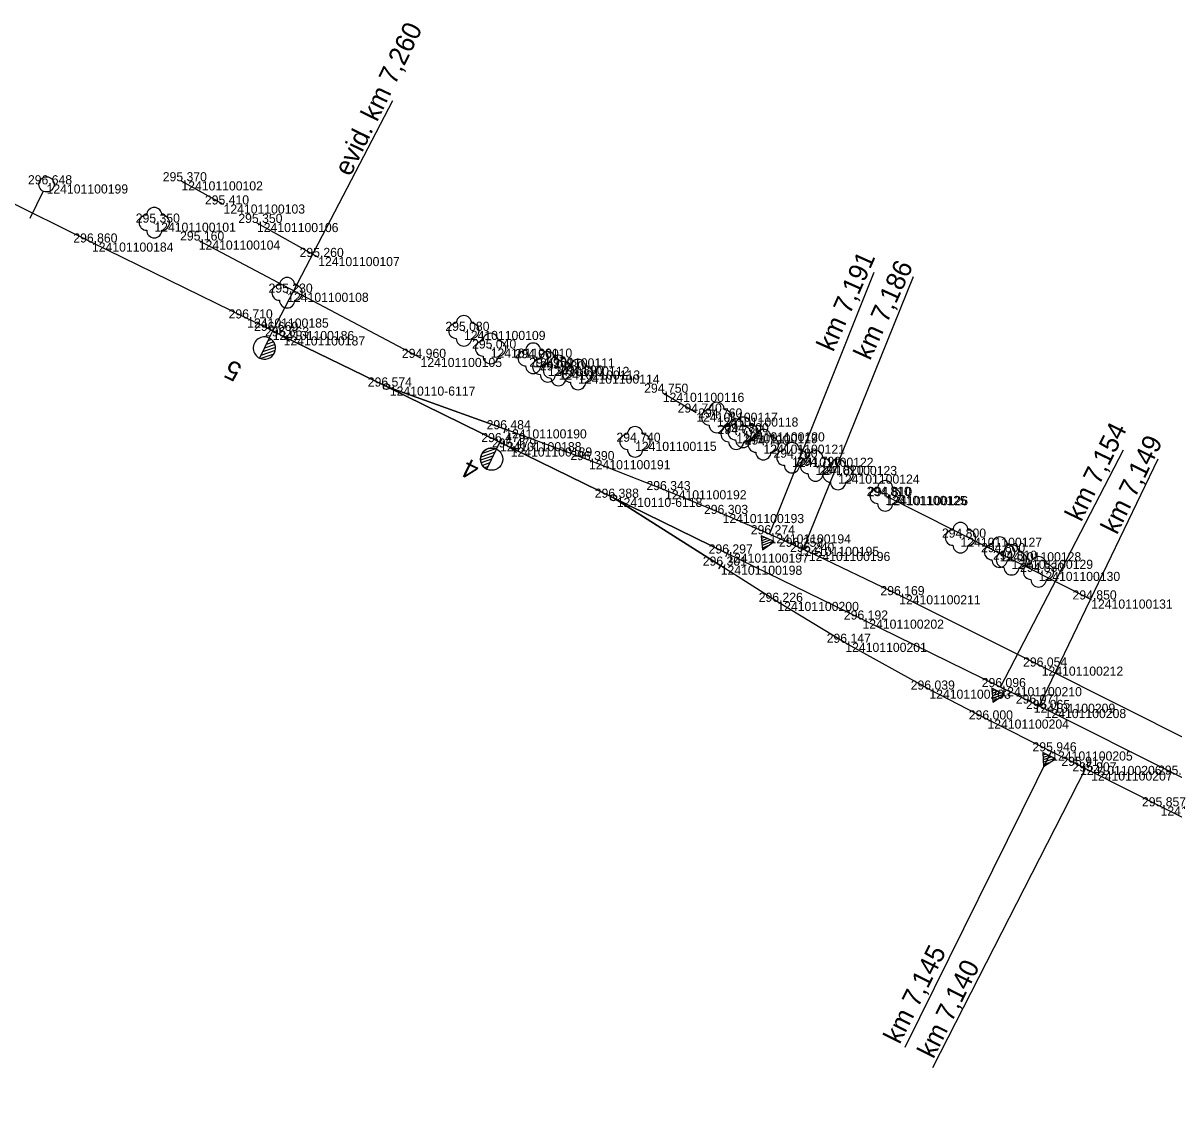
# Model space of a CAD drawing. Extents: x -616949 to -607976, y -1164436 to -1159224.
# Drawn here: x -613594.6 to -613443.4, y -1161463 to -1161320.7 of the extents above; entities that cross this region are included whole.
import ezdxf

# ---------------------------------------------------------------- set-up
doc = ezdxf.new("R2010")
doc.units = 0
for name, color, linetype in [('Vrstva 1', 7, 'Continuous'), ('Vrstva 2', 7, 'Continuous'), ('Vrstva 3', 7, 'Continuous'), ('Vrstva 37', 7, 'Continuous'), ('Vrstva 49', 7, 'Continuous'), ('Vrstva 50', 7, 'Continuous'), ('Vrstva 60', 7, 'Continuous'), ('Vrstva 61', 7, 'Continuous')]:
    doc.layers.add(name, color=color, linetype=linetype)

msp = doc.modelspace()

# ---------------------------------------------------------------- linework, layer by layer
at = {"layer": 'Vrstva 1'}
for points in [[(-613561.83, -1161361.12), (-613565.18, -1161359.48), (-613585.58, -1161349.51), (-613606, -1161339.42)], [(-613531.97, -1161375.72), (-613546.89, -1161368.42), (-613560.4, -1161361.83), (-613561.83, -1161361.12)], [(-613349.94, -1161460.64), (-613371.44, -1161449.88), (-613393.22, -1161439), (-613418.97, -1161426.12), (-613440.8, -1161415.2), (-613460.8, -1161405.2), (-613479.53, -1161395.83), (-613491.4, -1161390.14), (-613492.87, -1161389.47), (-613496.57, -1161387.83), (-613502.72, -1161385.16), (-613510.28, -1161382.03), (-613520.28, -1161378.09), (-613531.28, -1161374.04), (-613546.89, -1161368.42), (-613560.4, -1161361.83), (-613561.83, -1161361.12)], [(-613170.83, -1161560.95), (-613193.86, -1161549.42), (-613216.58, -1161538.05), (-613238.41, -1161527.12), (-613261.08, -1161515.78), (-613282.87, -1161504.88), (-613306.41, -1161493.08), (-613329.58, -1161481.52), (-613354.95, -1161468.79), (-613375.86, -1161458.34), (-613397.09, -1161447.7), (-613423.08, -1161434.66), (-613445.18, -1161423.56), (-613454.31, -1161418.97), (-613455.76, -1161418.24), (-613459.55, -1161416.34), (-613467.93, -1161412.15), (-613475.56, -1161408.23), (-613486.6, -1161402.08), (-613495.53, -1161396.7), (-613502.97, -1161391.95), (-613517.07, -1161383.03), (-613530.57, -1161376.42), (-613531.97, -1161375.72)], [(-613169.01, -1161556.54), (-613191.83, -1161545.12), (-613214.2, -1161533.93), (-613236.35, -1161522.85), (-613258.71, -1161511.65), (-613281.11, -1161500.45), (-613304.08, -1161488.95), (-613327.59, -1161477.18), (-613352.38, -1161464.78), (-613374.13, -1161453.9), (-613400.96, -1161440.47), (-613420.84, -1161430.52), (-613443.07, -1161419.4), (-613460.41, -1161410.77), (-613461.85, -1161410.06), (-613466.23, -1161407.9), (-613484.35, -1161399.03), (-613502.11, -1161390.35), (-613517.07, -1161383.03), (-613530.57, -1161376.42), (-613531.97, -1161375.72)]]:
    msp.add_lwpolyline(points, dxfattribs=at)
at = {"layer": 'Vrstva 2'}
for p, q in [((-613561.83, -1161361.12), (-613546.03, -1161330.84)), ((-613562.28, -1161362.05), (-613561.83, -1161361.12)), ((-613562.28, -1161362.05), (-613563.56, -1161364.68)), ((-613561.53, -1161362.91), (-613562.93, -1161363.4)), ((-613561.7, -1161362.57), (-613562.7, -1161362.91)), ((-613561.97, -1161362.26), (-613562.46, -1161362.43)), ((-613561.5, -1161363.71), (-613563.4, -1161364.36)), ((-613561.7, -1161364.18), (-613563.38, -1161364.76)), ((-613561.46, -1161363.29), (-613563.17, -1161363.88)), ((-613546.89, -1161368.42), (-613531.28, -1161374.04)), ((-613531.44, -1161374.51), (-613531.11, -1161373.57)), ((-613532.53, -1161376.61), (-613534.32, -1161377.22)), ((-613533.71, -1161379.28), (-613532.42, -1161376.65)), ((-613532.42, -1161376.65), (-613531.97, -1161375.72)), ((-613531.75, -1161375.27), (-613532.19, -1161376.17)), ((-613532.84, -1161377.51), (-613534.52, -1161378.08)), ((-613532.61, -1161377.03), (-613534.5, -1161377.68)), ((-613533.08, -1161377.98), (-613534.44, -1161378.45)), ((-613533.31, -1161378.46), (-613534.27, -1161378.79)), ((-613533.54, -1161378.94), (-613533.99, -1161379.09)), ((-613517.07, -1161383.03), (-613502.97, -1161391.95)), ((-613501.89, -1161389.9), (-613502.33, -1161390.8)), ((-613503.24, -1161392.37), (-613502.7, -1161391.53))]:
    msp.add_line(p, q, dxfattribs=at)
for points in [[(-613561.83, -1161361.12), (-613560.4, -1161361.83), (-613546.89, -1161368.42), (-613531.97, -1161375.72)], [(-613559.42, -1161362.02), (-613560.4, -1161361.83), (-613559.64, -1161362.48)], [(-613531.97, -1161375.72), (-613530.57, -1161376.42), (-613517.07, -1161383.03), (-613502.11, -1161390.35)], [(-613529.59, -1161376.62), (-613530.57, -1161376.42), (-613529.81, -1161377.08)]]:
    msp.add_lwpolyline(points, dxfattribs=at)
for centre, radius in [((-613546.89, -1161368.42), 0.4), ((-613533.07, -1161377.96), 1.46), ((-613517.07, -1161383.03), 0.4)]:
    msp.add_circle(centre, radius, dxfattribs=at)
for centre, start, end in [((-613562.93, -1161363.37), 63.7905, 244.26), ((-613562.92, -1161363.37), 244.0448, 64.0057), ((-613533.07, -1161377.96), 63.9691, 243.93)]:
    msp.add_arc(centre, 1.46, start, end, dxfattribs=at)
at = {"layer": 'Vrstva 3'}
for p, q in [((-613496.57, -1161387.83), (-613482.79, -1161353.4)), ((-613492.14, -1161389.81), (-613477.65, -1161353.99)), ((-613466.23, -1161407.9), (-613450.06, -1161376.73)), ((-613461.13, -1161410.42), (-613445.51, -1161377.91)), ((-613497.23, -1161388.21), (-613497.62, -1161388.36)), ((-613496.83, -1161388.39), (-613497.59, -1161388.68)), ((-613496.43, -1161388.56), (-613497.56, -1161389)), ((-613496.03, -1161388.74), (-613497.52, -1161389.31)), ((-613496.79, -1161389.35), (-613497.49, -1161389.63)), ((-613491.4, -1161390.14), (-613492.87, -1161389.47)), ((-613466.9, -1161408.26), (-613467.31, -1161408.39)), ((-613466.51, -1161408.45), (-613467.29, -1161408.72)), ((-613466.13, -1161408.64), (-613467.27, -1161409.03)), ((-613465.73, -1161408.83), (-613467.24, -1161409.35)), ((-613466.51, -1161409.42), (-613467.22, -1161409.67)), ((-613460.41, -1161410.77), (-613461.85, -1161410.06)), ((-613459.55, -1161416.34), (-613478.8, -1161455.25)), ((-613460.23, -1161416.69), (-613460.63, -1161416.82)), ((-613459.84, -1161416.88), (-613460.62, -1161417.14)), ((-613459.46, -1161417.07), (-613460.6, -1161417.46)), ((-613459.06, -1161417.27), (-613460.58, -1161417.77)), ((-613455.04, -1161418.6), (-613475.15, -1161457.89)), ((-613459.85, -1161417.85), (-613460.56, -1161418.09)), ((-613454.31, -1161418.97), (-613455.76, -1161418.24))]:
    msp.add_line(p, q, dxfattribs=at)
for points in [[(-613497.47, -1161389.85), (-613495.97, -1161388.77), (-613497.66, -1161388.01)], [(-613467.21, -1161409.89), (-613465.67, -1161408.87), (-613467.33, -1161408.05)], [(-613460.55, -1161418.32), (-613459, -1161417.3), (-613460.66, -1161416.47)]]:
    msp.add_lwpolyline(points, close=True, dxfattribs=at)
at = {"layer": 'Vrstva 37'}
for p, q in [((-613591.54, -1161341.87), (-613591.54, -1161341.87)), ((-613591.98, -1161342.77), (-613593.75, -1161346.35))]:
    msp.add_line(p, q, dxfattribs=at)
msp.add_circle((-613591.54, -1161341.87), 1, dxfattribs=at)
at = {"layer": 'Vrstva 49'}
for p, q in [((-613563.9, -1161346.94), (-613555.85, -1161351.41)), ((-613571.55, -1161349.24), (-613542.41, -1161364.66)), ((-613510.58, -1161369.24), (-613506.18, -1161371.85)), ((-613481.18, -1161382.83), (-613454.3, -1161396.39))]:
    msp.add_line(p, q, dxfattribs=at)
msp.add_lwpolyline([(-613568.29, -1161344.51), (-613573.83, -1161341.47)], dxfattribs=at)
at = {"layer": 'Vrstva 50'}
for p, q in [((-613577.45, -1161346.9), (-613577.31, -1161346.9)), ((-613560, -1161356.1), (-613559.86, -1161356.1)), ((-613536.77, -1161361.11), (-613536.63, -1161361.11)), ((-613533.26, -1161363.43), (-613533.11, -1161363.43)), ((-613527.67, -1161364.71), (-613527.53, -1161364.71)), ((-613525.75, -1161365.83), (-613525.61, -1161365.83)), ((-613524.34, -1161366.31), (-613524.2, -1161366.31)), ((-613521.78, -1161366.85), (-613521.64, -1161366.85)), ((-613503.55, -1161372.49), (-613503.41, -1161372.49)), ((-613501, -1161374.67), (-613500.86, -1161374.67)), ((-613500.08, -1161374.43), (-613499.94, -1161374.43)), ((-613514.29, -1161375.68), (-613514.15, -1161375.68)), ((-613497.43, -1161376.05), (-613497.29, -1161376.05)), ((-613493.67, -1161377.77), (-613493.53, -1161377.77)), ((-613490.58, -1161378.85), (-613490.44, -1161378.85)), ((-613487.62, -1161379.98), (-613487.48, -1161379.98)), ((-613481.42, -1161382.78), (-613481.28, -1161382.78)), ((-613471.53, -1161388.27), (-613471.39, -1161388.27)), ((-613466.39, -1161390.18), (-613466.25, -1161390.18)), ((-613464.83, -1161391.17), (-613464.69, -1161391.17)), ((-613461.27, -1161392.76), (-613461.13, -1161392.76))]:
    msp.add_line(p, q, dxfattribs=at)
for centre, start, end in [((-613577.39, -1161345.9), 0, 180), ((-613578.39, -1161346.9), 90, 270), ((-613576.39, -1161346.9), 270, 90), ((-613577.39, -1161347.9), 180, 0), ((-613560.94, -1161356.1), 90, 270), ((-613559.94, -1161355.1), 0, 180), ((-613558.94, -1161356.1), 270, 90), ((-613559.94, -1161357.1), 180, 0), ((-613537.71, -1161361.11), 90, 270), ((-613536.71, -1161360.11), 0, 180), ((-613535.71, -1161361.11), 270, 90), ((-613533.2, -1161362.43), 0, 180), ((-613536.71, -1161362.11), 180, 0), ((-613534.2, -1161363.43), 90, 270), ((-613532.2, -1161363.43), 270, 90), ((-613527.61, -1161363.71), 0, 180), ((-613533.2, -1161364.43), 180, 0), ((-613528.61, -1161364.71), 90, 270), ((-613525.69, -1161364.83), 0, 180), ((-613526.61, -1161364.71), 270, 90), ((-613524.28, -1161365.31), 0, 180), ((-613527.61, -1161365.71), 180, 0), ((-613526.69, -1161365.83), 90, 270), ((-613525.28, -1161366.31), 90, 270), ((-613524.69, -1161365.83), 270, 90), ((-613522.72, -1161366.85), 90, 270), ((-613523.28, -1161366.31), 270, 90), ((-613521.72, -1161365.85), 0, 180), ((-613520.72, -1161366.85), 270, 90), ((-613525.69, -1161366.83), 180, 0), ((-613524.28, -1161367.31), 180, 0), ((-613521.72, -1161367.85), 180, 0), ((-613503.49, -1161371.49), 0, 180), ((-613504.49, -1161372.49), 90, 270), ((-613502.49, -1161372.49), 270, 90), ((-613514.23, -1161374.68), 0, 180), ((-613503.49, -1161373.49), 180, 0), ((-613501.94, -1161374.67), 90, 270), ((-613501.02, -1161374.43), 90, 270), ((-613500.94, -1161373.67), 0, 180), ((-613500.02, -1161373.43), 0, 180), ((-613499.94, -1161374.67), 270, 90), ((-613499.02, -1161374.43), 270, 90), ((-613515.23, -1161375.68), 90, 270), ((-613513.23, -1161375.68), 270, 90), ((-613498.37, -1161376.05), 90, 270), ((-613497.37, -1161375.05), 0, 180), ((-613496.37, -1161376.05), 270, 90), ((-613514.23, -1161376.68), 180, 0), ((-613500.94, -1161375.67), 180, 0), ((-613500.02, -1161375.43), 180, 0), ((-613493.61, -1161376.77), 0, 180), ((-613497.37, -1161377.05), 180, 0), ((-613494.61, -1161377.77), 90, 270), ((-613492.61, -1161377.77), 270, 90), ((-613491.52, -1161378.85), 90, 270), ((-613490.52, -1161377.85), 0, 180), ((-613489.52, -1161378.85), 270, 90), ((-613487.56, -1161378.98), 0, 180), ((-613493.61, -1161378.77), 180, 0), ((-613488.56, -1161379.98), 90, 270), ((-613486.56, -1161379.98), 270, 90), ((-613490.52, -1161379.85), 180, 0), ((-613487.56, -1161380.98), 180, 0), ((-613481.36, -1161381.78), 0, 180), ((-613482.36, -1161382.78), 90, 270), ((-613480.36, -1161382.78), 270, 90), ((-613481.36, -1161383.78), 180, 0), ((-613472.47, -1161388.27), 90, 270), ((-613471.47, -1161387.27), 0, 180), ((-613470.47, -1161388.27), 270, 90), ((-613466.33, -1161389.18), 0, 180), ((-613471.47, -1161389.27), 180, 0), ((-613467.33, -1161390.18), 90, 270), ((-613465.77, -1161391.17), 90, 270), ((-613464.77, -1161390.17), 0, 180), ((-613465.33, -1161390.18), 270, 90), ((-613463.77, -1161391.17), 270, 90), ((-613466.33, -1161391.18), 180, 0), ((-613462.21, -1161392.76), 90, 270), ((-613461.21, -1161391.76), 0, 180), ((-613460.21, -1161392.76), 270, 90), ((-613464.77, -1161392.17), 180, 0), ((-613461.21, -1161393.76), 180, 0)]:
    msp.add_arc(centre, 1, start, end, dxfattribs=at)
at = {"layer": 'Vrstva 60'}
for p, q in [((-613591.54, -1161341.87), (-613591.54, -1161341.87)), ((-613573.83, -1161341.47), (-613573.83, -1161341.47)), ((-613568.29, -1161344.51), (-613568.29, -1161344.51)), ((-613577.38, -1161346.9), (-613577.38, -1161346.9)), ((-613563.9, -1161346.94), (-613563.9, -1161346.94)), ((-613585.58, -1161349.51), (-613585.58, -1161349.51)), ((-613571.55, -1161349.24), (-613571.55, -1161349.24)), ((-613555.85, -1161351.41), (-613555.85, -1161351.41)), ((-613559.93, -1161356.1), (-613559.93, -1161356.1)), ((-613565.18, -1161359.48), (-613565.18, -1161359.48)), ((-613561.83, -1161361.12), (-613561.83, -1161361.12)), ((-613536.7, -1161361.11), (-613536.7, -1161361.11)), ((-613560.4, -1161361.83), (-613560.4, -1161361.83)), ((-613533.19, -1161363.43), (-613533.19, -1161363.43)), ((-613542.41, -1161364.66), (-613542.41, -1161364.66)), ((-613527.6, -1161364.71), (-613527.6, -1161364.71)), ((-613525.68, -1161365.83), (-613525.68, -1161365.83)), ((-613524.27, -1161366.31), (-613524.27, -1161366.31)), ((-613521.71, -1161366.85), (-613521.71, -1161366.85)), ((-613546.89, -1161368.42), (-613546.89, -1161368.42)), ((-613510.58, -1161369.24), (-613510.58, -1161369.24)), ((-613506.18, -1161371.85), (-613506.18, -1161371.85)), ((-613503.48, -1161372.49), (-613503.48, -1161372.49)), ((-613531.28, -1161374.04), (-613531.28, -1161374.04)), ((-613500.93, -1161374.67), (-613500.93, -1161374.67)), ((-613500.01, -1161374.43), (-613500.01, -1161374.43)), ((-613531.97, -1161375.72), (-613531.97, -1161375.72)), ((-613530.57, -1161376.42), (-613530.57, -1161376.42)), ((-613514.22, -1161375.68), (-613514.22, -1161375.68)), ((-613497.36, -1161376.05), (-613497.36, -1161376.05)), ((-613520.28, -1161378.09), (-613520.28, -1161378.09)), ((-613493.6, -1161377.77), (-613493.6, -1161377.77)), ((-613490.51, -1161378.85), (-613490.51, -1161378.85)), ((-613487.55, -1161379.98), (-613487.55, -1161379.98)), ((-613510.28, -1161382.03), (-613510.28, -1161382.03)), ((-613481.35, -1161382.78), (-613481.35, -1161382.78)), ((-613517.07, -1161383.03), (-613517.07, -1161383.03)), ((-613481.18, -1161382.83), (-613481.18, -1161382.83)), ((-613502.72, -1161385.16), (-613502.72, -1161385.16)), ((-613496.57, -1161387.83), (-613496.57, -1161387.83)), ((-613471.46, -1161388.27), (-613471.46, -1161388.27)), ((-613502.11, -1161390.35), (-613502.11, -1161390.35)), ((-613492.87, -1161389.47), (-613492.87, -1161389.47)), ((-613491.4, -1161390.14), (-613491.4, -1161390.14)), ((-613466.32, -1161390.18), (-613466.32, -1161390.18)), ((-613464.76, -1161391.17), (-613464.76, -1161391.17)), ((-613502.97, -1161391.95), (-613502.97, -1161391.95)), ((-613461.2, -1161392.76), (-613461.2, -1161392.76)), ((-613479.53, -1161395.83), (-613479.53, -1161395.83)), ((-613454.3, -1161396.39), (-613454.3, -1161396.39)), ((-613495.53, -1161396.7), (-613495.53, -1161396.7)), ((-613484.35, -1161399.03), (-613484.35, -1161399.03)), ((-613486.6, -1161402.08), (-613486.6, -1161402.08)), ((-613460.8, -1161405.2), (-613460.8, -1161405.2)), ((-613475.56, -1161408.23), (-613475.56, -1161408.23)), ((-613466.23, -1161407.9), (-613466.23, -1161407.9)), ((-613461.85, -1161410.06), (-613461.85, -1161410.06)), ((-613460.41, -1161410.77), (-613460.41, -1161410.77)), ((-613467.93, -1161412.15), (-613467.93, -1161412.15)), ((-613459.55, -1161416.34), (-613459.55, -1161416.34)), ((-613455.76, -1161418.24), (-613455.76, -1161418.24)), ((-613454.31, -1161418.97), (-613454.31, -1161418.97)), ((-613445.18, -1161423.56), (-613445.18, -1161423.56))]:
    msp.add_line(p, q, dxfattribs=at)

# ---------------------------------------------------------------- texts
at = {"layer": 'Vrstva 2'}
for s, rotation, p in [('evid. km 7,260', 64.0253, (-613551.63, -1161340.94)), ('5', 154.0253, (-613565.69, -1161365.64)), ('4', 153.95, (-613534.48, -1161378.62))]:
    msp.add_text(s, height=2.5, rotation=rotation, dxfattribs=at).set_placement(p)
at = {"layer": 'Vrstva 3'}
for s, rotation, p in [('km 7,191', 66.003, (-613488.2, -1161363.98)), ('km 7,186', 65.5181, (-613483.35, -1161365.1)), ('km 7,154', 63.7495, (-613455.62, -1161386.3)), ('km 7,149', 63.8193, (-613450.92, -1161387.98)), ('km 7,145', 63.3143, (-613479.47, -1161454.91)), ('km 7,140', 63.4349, (-613475.03, -1161456.83))]:
    msp.add_text(s, height=2.5, rotation=rotation, dxfattribs=at).set_placement(p)
at = {"layer": 'Vrstva 60'}
for s, p in [('124101100199', (-613591.54, -1161343.07)), ('124101100102', (-613573.83, -1161342.67)), ('124101100103', (-613568.29, -1161345.71)), ('124101100101', (-613577.38, -1161348.1)), ('124101100106', (-613563.9, -1161348.14)), ('124101100184', (-613585.58, -1161350.71)), ('124101100104', (-613571.55, -1161350.44)), ('124101100107', (-613555.85, -1161352.61)), ('124101100108', (-613559.93, -1161357.3)), ('124101100185', (-613565.18, -1161360.68)), ('124101100186', (-613561.83, -1161362.32)), ('124101100109', (-613536.7, -1161362.31)), ('124101100187', (-613560.4, -1161363.03)), ('124101100105', (-613542.41, -1161365.86)), ('124101100110', (-613533.19, -1161364.63)), ('124101100111', (-613527.6, -1161365.91)), ('124101100112', (-613525.68, -1161367.03)), ('124101100113', (-613524.27, -1161367.51)), ('124101100114', (-613521.71, -1161368.05)), (' 12410110-6117', (-613546.89, -1161369.62)), ('124101100116', (-613510.58, -1161370.44)), ('124101100117', (-613506.18, -1161373.05)), ('124101100118', (-613503.48, -1161373.69)), ('124101100190', (-613531.28, -1161375.24)), ('124101100119', (-613500.93, -1161375.87)), ('124101100120', (-613500.01, -1161375.63)), ('124101100188', (-613531.97, -1161376.92)), ('124101100189', (-613530.57, -1161377.62)), ('124101100115', (-613514.22, -1161376.88)), ('124101100121', (-613497.36, -1161377.25)), ('124101100191', (-613520.28, -1161379.29)), ('124101100122', (-613493.6, -1161378.97)), ('124101100123', (-613490.51, -1161380.05)), ('124101100124', (-613487.55, -1161381.18)), ('124101100192', (-613510.28, -1161383.24)), ('124101100125', (-613481.35, -1161383.98)), (' 12410110-6118', (-613517.07, -1161384.23)), ('124101100126', (-613481.18, -1161384.03)), ('124101100193', (-613502.72, -1161386.36)), ('124101100194', (-613496.57, -1161389.03)), ('124101100127', (-613471.46, -1161389.47)), ('124101100197', (-613502.11, -1161391.55)), ('124101100195', (-613492.87, -1161390.67)), ('124101100196', (-613491.4, -1161391.34)), ('124101100128', (-613466.32, -1161391.38)), ('124101100129', (-613464.76, -1161392.37)), ('124101100198', (-613502.97, -1161393.15)), ('124101100130', (-613461.2, -1161393.96)), ('124101100211', (-613479.53, -1161397.03)), ('124101100131', (-613454.3, -1161397.59)), ('124101100200', (-613495.53, -1161397.9)), ('124101100202', (-613484.35, -1161400.23)), ('124101100201', (-613486.6, -1161403.28)), ('124101100212', (-613460.8, -1161406.4)), ('124101100203', (-613475.56, -1161409.43)), ('124101100210', (-613466.23, -1161409.1)), ('124101100209', (-613461.85, -1161411.27)), ('124101100208', (-613460.41, -1161411.97)), ('124101100204', (-613467.93, -1161413.35)), ('124101100205', (-613459.55, -1161417.54)), ('124101100206', (-613455.76, -1161419.44)), ('124101100207', (-613454.31, -1161420.17)), ('124101100215', (-613445.18, -1161424.76))]:
    msp.add_text(s, height=1.2, dxfattribs=at).set_placement(p)
at = {"layer": 'Vrstva 61'}
for s, p in [('295.370', (-613576.28, -1161341.47)), ('296.648', (-613593.99, -1161341.87)), ('295.410', (-613570.74, -1161344.51)), ('295.350', (-613579.83, -1161346.9)), ('295.350', (-613566.35, -1161346.94)), ('296.860', (-613588.03, -1161349.51)), ('295.160', (-613574, -1161349.24)), ('295.260', (-613558.3, -1161351.41)), ('295.230', (-613562.38, -1161356.1)), ('296.710', (-613567.63, -1161359.48)), ('296.669', (-613564.28, -1161361.12)), ('295.080', (-613539.15, -1161361.11)), ('296.663', (-613562.85, -1161361.83)), ('295.040', (-613535.64, -1161363.43)), ('294.960', (-613544.86, -1161364.66)), ('294.960', (-613530.05, -1161364.71)), ('294.950', (-613528.13, -1161365.83)), ('294.930', (-613526.72, -1161366.31)), ('294.890', (-613524.16, -1161366.85)), ('296.574', (-613549.34, -1161368.42)), ('294.750', (-613513.03, -1161369.24)), ('294.740', (-613508.63, -1161371.85)), ('294.760', (-613505.93, -1161372.49)), ('296.484', (-613533.73, -1161374.04)), ('294.770', (-613503.38, -1161374.67)), ('294.800', (-613502.46, -1161374.43)), ('296.479', (-613534.43, -1161375.72)), ('296.479', (-613533.02, -1161376.42)), ('294.740', (-613516.67, -1161375.68)), ('294.790', (-613499.81, -1161376.05)), ('294.780', (-613496.05, -1161377.77)), ('296.390', (-613522.73, -1161378.09)), ('294.790', (-613492.96, -1161378.85)), ('294.820', (-613490, -1161379.98)), ('296.343', (-613512.73, -1161382.03)), ('296.388', (-613519.52, -1161383.03)), ('294.810', (-613483.8, -1161382.78)), ('294.810', (-613483.63, -1161382.83)), ('296.303', (-613505.17, -1161385.16)), ('296.274', (-613499.02, -1161387.83)), ('294.800', (-613473.91, -1161388.27)), ('296.253', (-613495.33, -1161389.47)), ('296.297', (-613504.56, -1161390.35)), ('296.240', (-613493.85, -1161390.14)), ('294.800', (-613468.77, -1161390.18)), ('294.810', (-613467.21, -1161391.17)), ('296.301', (-613505.33, -1161391.95)), ('294.830', (-613463.65, -1161392.76)), ('296.169', (-613481.99, -1161395.83)), ('296.226', (-613497.98, -1161396.7)), ('294.850', (-613456.75, -1161396.39)), ('296.192', (-613486.79, -1161399.03)), ('296.147', (-613489.05, -1161402.08)), ('296.054', (-613463.25, -1161405.2)), ('296.096', (-613468.68, -1161407.9)), ('296.039', (-613478.01, -1161408.23)), ('296.071', (-613464.2, -1161410.06)), ('296.065', (-613462.87, -1161410.77)), ('296.000', (-613470.38, -1161412.15)), ('295.946', (-613462.01, -1161416.34)), ('295.917', (-613458.21, -1161418.24)), ('295.907', (-613456.77, -1161418.97)), ('295.994', (-613445.52, -1161419.4)), ('295.857', (-613447.63, -1161423.56))]:
    msp.add_text(s, height=1.2, dxfattribs=at).set_placement(p)

doc.saveas('drawing.dxf')
